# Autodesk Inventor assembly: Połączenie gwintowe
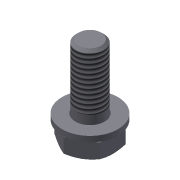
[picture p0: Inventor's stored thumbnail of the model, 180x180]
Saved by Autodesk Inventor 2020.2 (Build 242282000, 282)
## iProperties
Created: 2010-09
Part Number: Połączenie gwintowe
Document SubType Name: Assembly
Designer: F.Stasiak
ClientObjectVersion: 1
Manager: www.cadconsulting.pl
Company: Fabian Stasiak CAD Consulting
Author: F.Stasiak
Subject: Zbiór ćwiczeń. Autodesk Inventor 2020. Kurs podstawowy
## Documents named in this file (3)
- C:\2020_Kurs_podstawowy\R9 Zarządzanie plikami\369-000\Design Accelerator\Połączenie gwintowe1.iam
- C:\2020_Kurs_podstawowy\Zasoby\Content Center Files\pl-PL\ISO 7089\ISO 7089 - 8 - 140 HV(1).ipt
- C:\2020_Kurs_podstawowy\Zasoby\Content Center Files\pl-PL\ISO 4017(1)\ISO 4017 - M8 x 20ISO.ipt
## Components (2 placed, 2 different names)
1. ISO 7089 8 - 140 HV:1
2. ISO 4017 M8 x 20:1
